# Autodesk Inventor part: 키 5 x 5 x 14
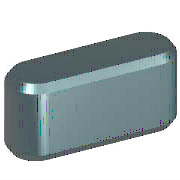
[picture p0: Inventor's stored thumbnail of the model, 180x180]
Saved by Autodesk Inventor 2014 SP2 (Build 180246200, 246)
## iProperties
Created: 2012-02
Part Number: 키 5 x 5 x 14
Material: 강철, 연강
Description: 키 및 해당 키홈
Document SubType Name: Modeling
Standard: KS B 1311
Designer: mduedu
Standards Organization: KS
Language: ko-KR
Size Designation: 5 x 5 x 14
Categories: <MemberInstance><Categories><Category DisplayName="샤프트 부품" InternalName="7f7aeb1f-a693-4053-b835-cee3144e0d98" Mnemonic="SHFT"><Category DisplayName="키" Interna
Density: 1 g/cm^3
Appearance: 노란색
IsCustomPart: 1
Author: mduedu
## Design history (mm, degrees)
workplane "Work Plane1"
workplane "Work Plane2"
sketch "스케치1"
  geometry: L1 (2.5, 2.5)-(11.5, 2.5); L2 (11.5, -2.5)-(2.5, -2.5); L3 (0, 9.4)-(0, -7.4) reference; L4 (-5, 0)-(30, 0) reference; L5 (14, 0)-(14, 7); A1 r 2.5 centre (2.5, 0) between (2.5, 2.5) and (2.5, -2.5); A2 r 2.5 centre (11.5, 0) between (11.5, -2.5) and (11.5, 2.5)
  constraints: 6 end point, 5 point on circle, 4 tangent, 3 point on line, 2 centre point, 1 horizontal, 1 parallel, 1 perpendicular
  dimensions: "d0" = 2.5 radius of A1 (= 0.5 x PB); "d13" = 2.5 radius of A2 (= 0.5 x PB); "d14" = 14 distance between parallel lines of L5 L3 (= NLG)
extrude "본체1" new body sketch "스케치1" taper "d3" = 0 deg; stored distance "d4" = 10
workplane "Work Plane3"
body "Solid1"
chamfer "모따기1" distance "d8" = 0.4 (= PHH); stored, may be unused: second distance "d9" = 0.4 (= PHH), angle "d15" = 45 deg
other parameters: "d1" = -3 (= -PNT), "d2" = 2 (= PH - PNT), "NLG" = 14 [user parameter; used in 3 equation terms], "PB" = 5 [user parameter; used in 2 equation terms], "PNT" = 3 [user parameter; used in 2 equation terms], "PH" = 5 [user parameter; used in 1 equation term], "PHH" = 0.4 [user parameter; used in 2 equation terms], "d10" = 0, "d16" = 0, "d17" = 0, "d18" = 0, "WDMIN" = 12 [user parameter], "PLB2" = 14 (= NLG) [user parameter], "WDMAX" = 17 [user parameter], "PLB1" = 14 (= NLG) [user parameter], "RR" = 0.16 [user parameter], "PUEB" = 2.3 [user parameter]
